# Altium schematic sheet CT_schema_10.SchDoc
size 308 x 210 mm
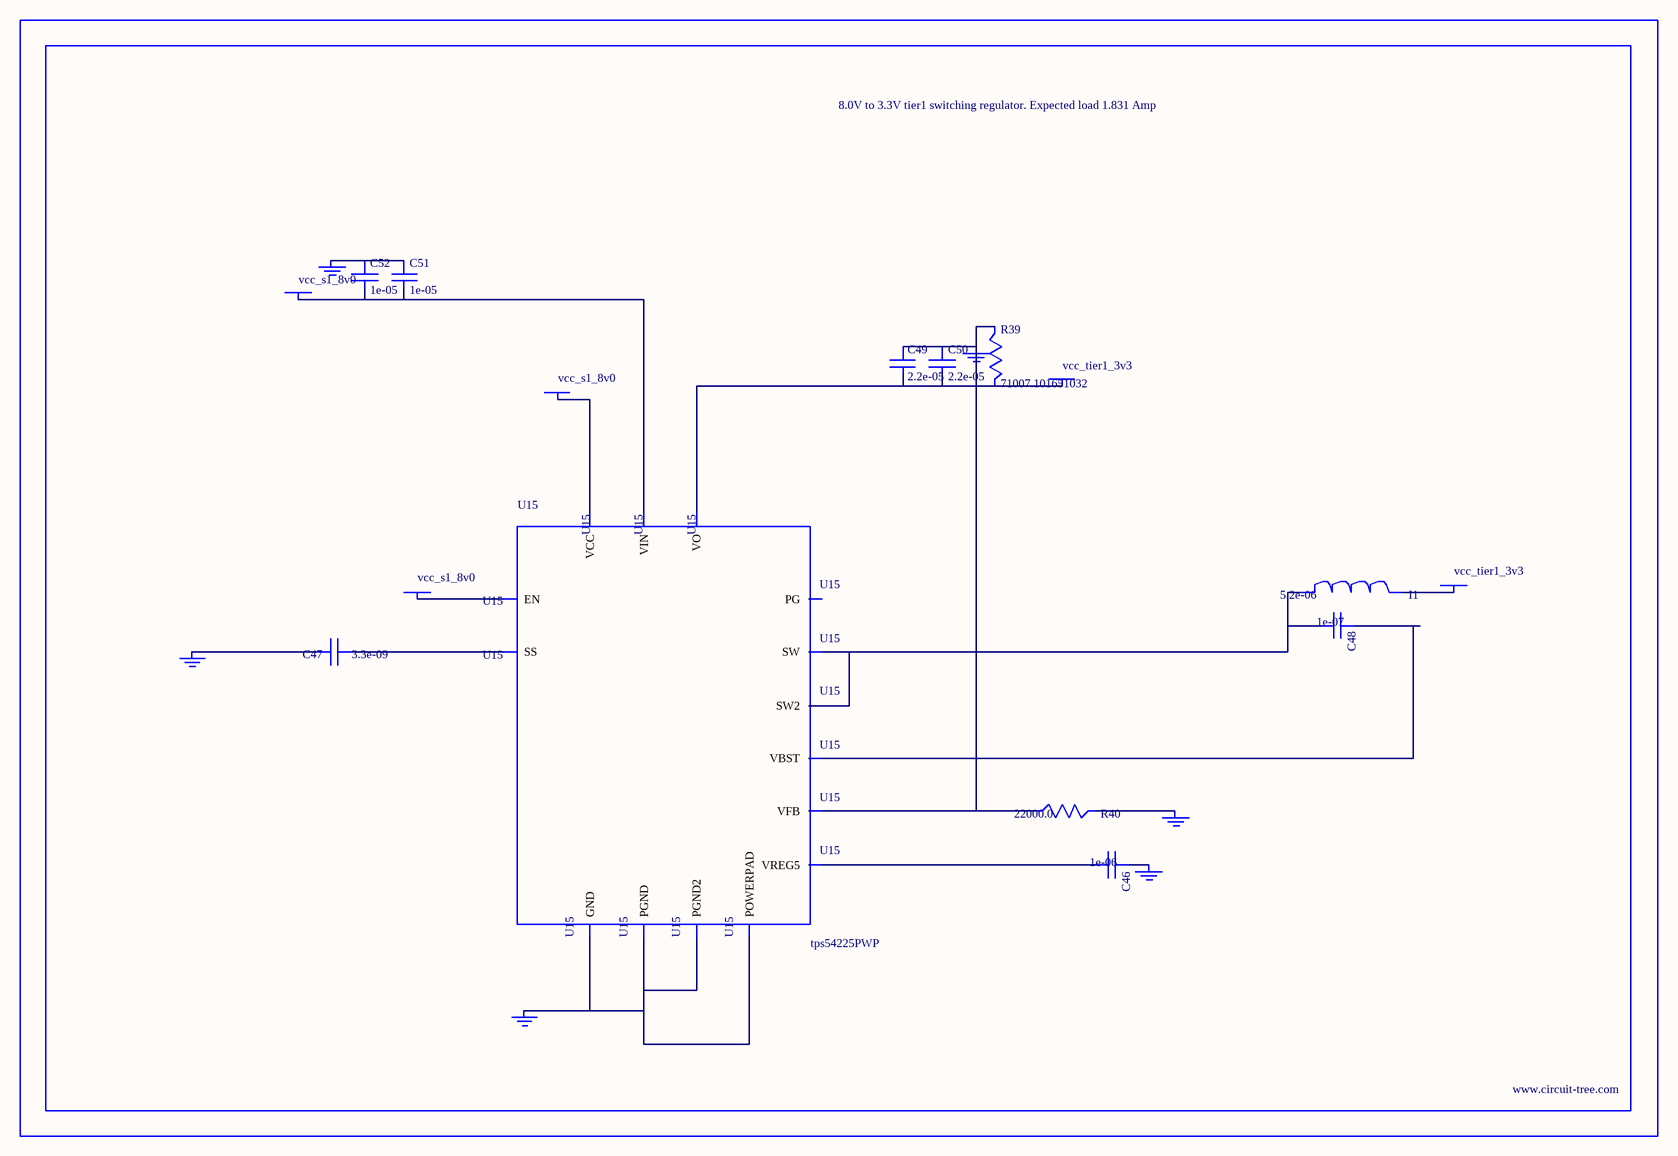
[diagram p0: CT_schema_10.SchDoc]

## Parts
BORDER9  (no value)
C46  1e-06  [C0603]
C47  3.3e-09  [C0402]
C48  1e-07  [C0402]
C49  2.2e-05  [C1210]
C50  2.2e-05  [C1210]
C51  1e-05  [C1206]
C52  1e-05  [C1206]
GND_INSTANCE_9_0  (no value)
GND_INSTANCE_9_1  (no value)
GND_INSTANCE_9_2  (no value)
GND_INSTANCE_9_3  (no value)
GND_INSTANCE_9_4  (no value)
GND_INSTANCE_9_5  (no value)
I1  5.2e-06  [DR1040]
POWER_INSTANCE_9_0  vcc_tier1_3v3
POWER_INSTANCE_9_1  vcc_s1_8v0
POWER_INSTANCE_9_2  vcc_tier1_3v3
POWER_INSTANCE_9_3  vcc_s1_8v0
POWER_INSTANCE_9_4  vcc_s1_8v0
R39  71007.101651032  [R0603]
R40  22000.0  [R0603]
U15  tps54225PWP  [HTSSOP14]

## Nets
NetC46_1: C46.1 GND_INSTANCE_9_2.0(GND)
NetC46_2: C46.2 U15.3(VREG5)
NetC47_1: C47.1 U15.4(SS)
NetC47_2: C47.2 GND_INSTANCE_9_3.0(GND)
NetC48_1: C48.1 U15.12(VBST)
NetC48_2: C48.2 I1.1 U15.10(SW) U15.11(SW2)
NetC49_1: C49.1 C50.1 GND_INSTANCE_9_0.0(GND) R39.1 R40.1 U15.2(VFB)
NetC49_2: C49.2 C50.2 POWER_INSTANCE_9_0.0(PWR) R39.2 U15.1(VO)
NetC51_1: C51.1 C52.1 GND_INSTANCE_9_5.0(GND)
NetC51_2: C51.2 C52.2 POWER_INSTANCE_9_3.0(PWR) U15.13(VIN)
NetGND_INSTANCE_9_1_0: GND_INSTANCE_9_1.0(GND) R40.2
NetGND_INSTANCE_9_4_0: GND_INSTANCE_9_4.0(GND) U15.5(GND) U15.8(PGND) U15.9(PGND2) U15.15(POWERPAD)
NetI1_2: I1.2 POWER_INSTANCE_9_2.0(PWR)
NetPOWER_INSTANCE_9_1_0: POWER_INSTANCE_9_1.0(PWR) U15.7(EN)
NetPOWER_INSTANCE_9_4_0: POWER_INSTANCE_9_4.0(PWR) U15.14(VCC)

Not connected (* = marked no-connect by the designer): U15 6(PG)

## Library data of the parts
BORDER9 = BORDER_PAGE9
C46 = C0603C105K3RACTU
C47 = C0402C332K3RAC
C48 = C0402C104K3RACTU
C49 C50 = GRM32ER61E226ME15L
C51 C52 = C1206C106K3RACTU
GND_INSTANCE_9_0-GND_INSTANCE_9_5 = GND
I1 = DR1040-5R2-R
POWER_INSTANCE_9_0-POWER_INSTANCE_9_4 = PWR
R39 = R39
R40 = RC0603JR-0722KL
